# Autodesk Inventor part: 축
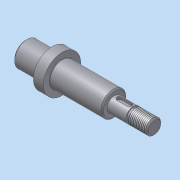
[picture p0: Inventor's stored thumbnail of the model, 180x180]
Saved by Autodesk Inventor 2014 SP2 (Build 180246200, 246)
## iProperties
Created: 2015-03
Part Number: 축
Material: 강
Document SubType Name: Modeling
Designer: KYOUNG IL JANG
Density: 1 g/cm^3
Appearance: 강철
CustomPartVersion: 1
Author: KYOUNG IL JANG
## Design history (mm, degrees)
sketch "스케치5"
  geometry: L1 (0, 0)-(103, 0); L2 (0, 0)-(103, 0); L3 (103, 0)-(103, 6); L4 (71, 6)-(71, 10); L5 (71, 10)-(29, 10); L6 (29, 10)-(29, 15); L7 (29, 15)-(21, 15); L8 (21, 15)-(21, 10); L9 (21, 10)-(0, 10); L10 (0, 10)-(0, 0); L11 (86, 6)-(86, 5); L12 (86, 5)-(88, 5); L13 (88, 5)-(88, 6); L14 (103, 6)-(88, 6); L15 (86, 6)-(71, 6)
  constraints: 31 end point, 12 perpendicular, 9 parallel, 1 collinear, 1 horizontal
  dimensions: "d43" = 20 diameter of L9 L1; "d44" = 30 diameter of L7 L1; "d45" = 20 diameter of L5 L2; "d47" = 8 distance of L6.end L7.end; "d48" = 32 distance between parallel lines of L3 L4; "d49" = 42 distance between parallel lines of L4 L6; "d50" = 21 distance of L8.end L9.end; "d52" = 12 diameter of L14 L1; "d53" = 15 distance between parallel lines of L3 L13; "d54" = 2 distance of L11.end L12.end; "d55" = 1 distance between parallel lines of L14 L12
revolve "회전4" sketch "스케치5" stored, may be unused: angle "d51" = 90 deg
feature "스레드6" dims "d56" = 10, "d57" = 0
chamfer "모따기6" distance "d32" = 1; stored, may be unused: second distance "d33" = 0.4, angle "d34" = 45 deg
chamfer "모따기5" distance "d27" = 1; stored, may be unused: second distance "d28" = 0.125, angle "d29" = 45 deg
fillet "모깎기1" dims "d17" = 0.3
fillet "모깎기2" dims "d18" = 0.3
chamfer "모따기3" distance "d19" = 1; stored, may be unused: second distance "d20" = 1, angle "d21" = 45 deg
node "작업 평면1"
sketch "스케치6"
  geometry: L1 (-3.5, 2)-(4.5, 2); L2 (4.5, -2)-(-3.5, -2); L3 (-7.5, 9)-(-7.5, -9) reference; A1 r 2 centre (4.5, 0) between (4.5, -2) and (4.5, 2); A2 r 2 centre (-3.5, 0) between (-3.5, 2) and (-3.5, -2); 1 further point
  constraints: 4 end point, 4 point on circle, 4 tangent, 2 centre point, 1 horizontal, 1 horizontal alignment, 1 parallel
  dimensions: "d59" = 2 distance edge to line of A2 L3; "d60" = 12 dimension on A1 A2; "d61" = 4 distance between parallel lines of L2 L1
extrude "돌출1" cut sketch "스케치6" distance "d62" = 2.3; taper "d63" = 0 deg
node "솔리드1"
node "솔리드2"
other parameters: "d46" = 12
